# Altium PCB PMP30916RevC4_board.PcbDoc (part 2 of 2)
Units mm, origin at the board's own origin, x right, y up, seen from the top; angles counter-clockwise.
Board outline 58.42 x 31.75 mm, 4 copper layers (Top Layer, Layer 2, Layer 3, Bottom Layer), stack 1.787 mm thick; 61 components, 27 nets, 160 pads, 105 vias.
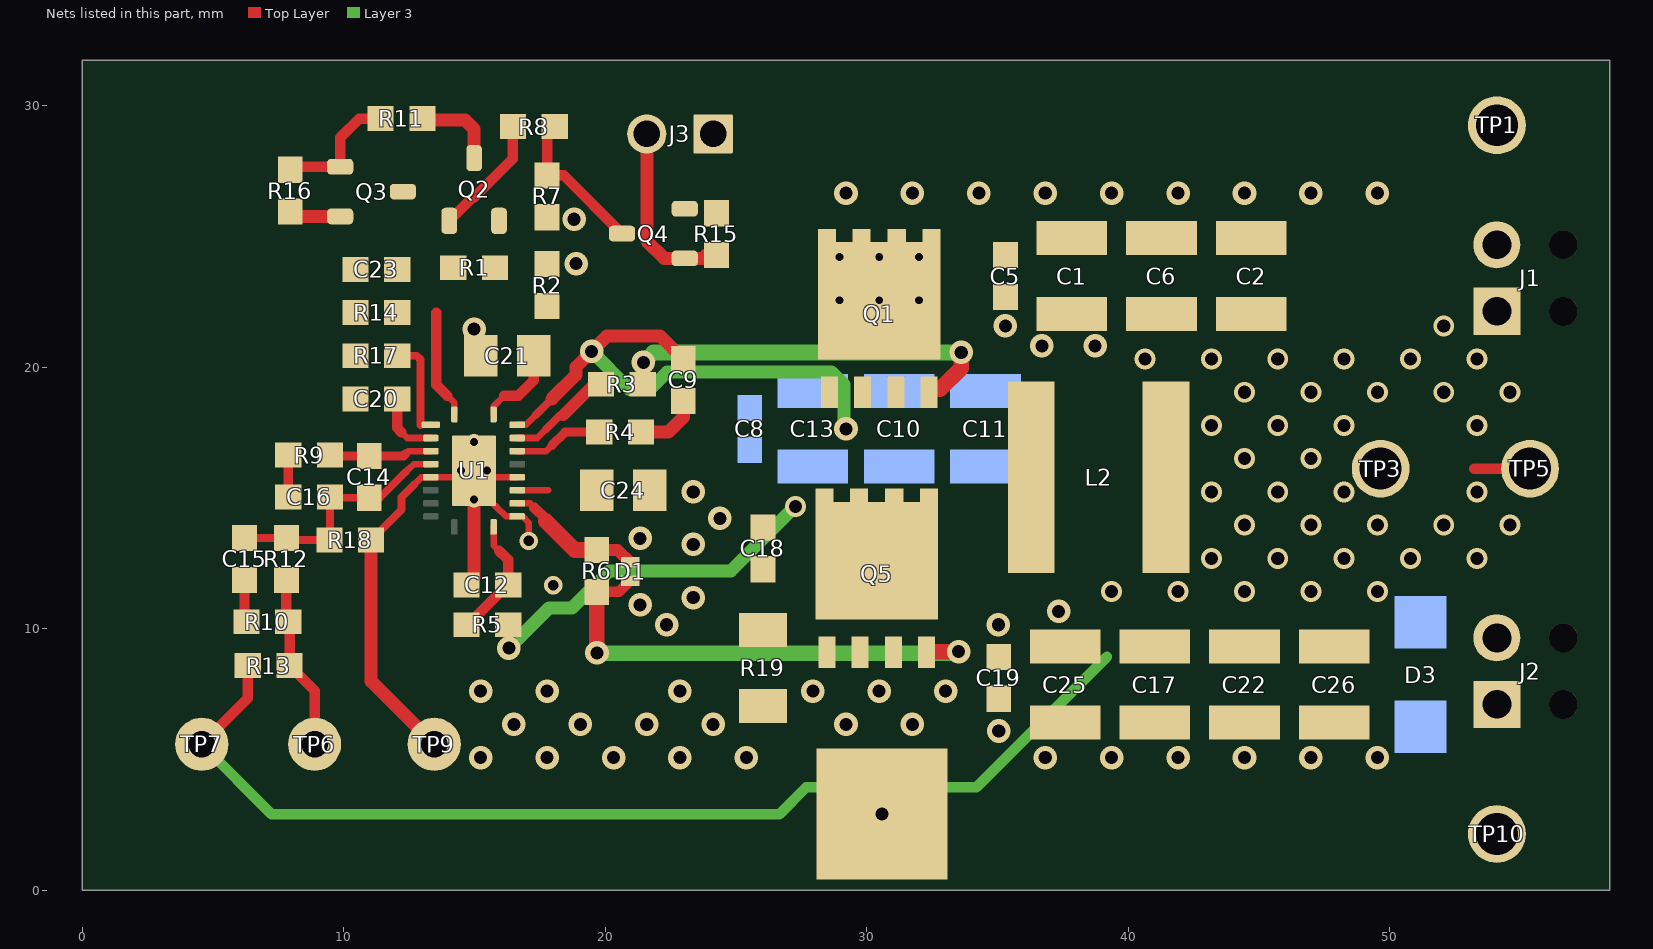
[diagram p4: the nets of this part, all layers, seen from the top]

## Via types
v1: diameter 0.9, hole 0.5, Top Layer to Bottom Layer, 35 vias
v2: diameter 0.8, hole 0.5, Top Layer to Bottom Layer, 31 vias
v3: diameter 0.9, hole 0.5, Top Layer to Bottom Layer, tented top, 18 vias
v4: diameter 0.8, hole 0.5, Top Layer to Bottom Layer, tented top, 7 vias
v5: diameter 0.7, hole 0.3, Top Layer to Bottom Layer, 6 vias
v6: diameter 0.6, hole 0.3, Top Layer to Bottom Layer, 4 vias
v7: diameter 0.7, hole 0.4, Top Layer to Bottom Layer, tented top, 2 vias
v8: diameter 0.9/0.9/0.9/0.8 (per signal layer), hole 0.5, Top Layer to Bottom Layer, tented bottom, 1 vias
v9: diameter 0.9, hole 0.5, Top Layer to Bottom Layer, tented both sides, 1 vias

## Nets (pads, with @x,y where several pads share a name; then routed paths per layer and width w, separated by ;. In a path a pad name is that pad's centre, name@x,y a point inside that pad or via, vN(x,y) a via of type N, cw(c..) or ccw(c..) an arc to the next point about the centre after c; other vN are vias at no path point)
GND: C1.2 C2.2 C5.2 C6.2 C17.2 C19.1 C22.2 C25.2 C26.2 D3.1 J1.1 J2.2 J3.1 L2.2 Q4.2 R13.2 R15.1 TP3.1 TP5.1 TP7.1 | length 44.1
  Top Layer w0.4: TP7.1@4.572,5.588 6.333,7.349 R13.2@6.333,8.598 ; 53.244,16.129 TP5.1@55.372,16.129 ; TP5.1@54.507,16.122 TP5.1@54.514,16.129
  Layer 3 w0.4: TP7.1@4.572,5.588 7.239,2.921 26.667,2.921 27.683,3.937 34.201,3.937 39.192,8.928
  other v2: 44.45,11.43 46.99,11.43 49.53,11.43 45.72,12.7 48.26,12.7 50.8,12.7 53.34,12.7 44.45,13.97 46.99,13.97 49.53,13.97 52.07,13.97 54.61,13.97 45.72,15.24 48.26,15.24 53.34,15.24 44.45,16.51 46.99,16.51 45.72,17.78 48.26,17.78 53.34,17.78 44.45,19.05 46.99,19.05 49.53,19.05 52.07,19.05 54.61,19.05 45.72,20.32 48.26,20.32 50.8,20.32 53.34,20.32 52.07,21.59
  other v3: 35.04,10.16 37.338,10.668 36.703,20.828 38.735,20.828 35.306,21.59
  other v4: 39.37,11.43 41.91,11.43 43.18,12.7 43.18,15.24 43.18,17.78 40.64,20.32 43.18,20.32
NetC1_1: C1.1 C2.1 C5.1 C6.1 C8.1 C10.1 C11.1 C13.1 J1.2 Q1.5 Q1.6 Q1.7 Q1.8 Q1.9 Q2.2 R1.2 R2.2 R7.2 TP1.1
  other v1: 18.886,23.97 29.21,26.67 31.75,26.67 34.29,26.67 36.83,26.67 39.37,26.67 41.91,26.67 44.45,26.67 46.99,26.67 49.53,26.67
  other v5: 28.956,22.568 30.48,22.568 32.004,22.568 28.956,24.219 30.48,24.219 32.004,24.219
  other v9: 18.811,25.668
NetC8_2: C8.2 C10.2 C11.2 C12.2 C13.2 C17.1 C19.2 C20.2 C21.2 C22.1 C23.2 C24.2 C25.1 C26.1 D3.2 J2.1 pad.12 Q3.2 Q5.1 Q5.2 Q5.3 R14.1 R16.1 R17.1 R18.1 R19.1 TP9.1 TP10.1 U1.6 U1.12 U1.15 U1.21@14.984,16.052 | length 23.9
  Top Layer w0.25: 12.7,15.526 12.977,15.802 U1.6@13.334,15.802 U1.21@14.334,15.802 ; U1.21@15.234,15.802 U1.15@16.634,15.802 ; U1.21@15.494,14.986 16.218,14.302 U1.12@16.634,14.302 16.844,14.302 17.082,14.064 v7(17.082,13.366) ; 15.834,14.686 15.834,14.691
  Top Layer w0.3: R18.1@11.051,13.401 12.209,14.559 12.209,15.035 12.7,15.526
  Top Layer w0.5: R16.1@7.958,25.958 8.141,25.775 Q3.2@9.866,25.775 ; R18.1@11.051,13.401 11.051,7.999 TP9.1@13.462,5.588 ; C12.2@14.694,11.684 14.984,11.974 v6(14.984,14.952) U1.21@14.984,16.052 U1.21@14.986,16.05
  other v1: 15.24,5.08 17.78,5.08 20.32,5.08 22.86,5.08 25.4,5.08 16.51,6.35 19.05,6.35 21.59,6.35 24.13,6.35 29.21,6.35 31.75,6.35 15.24,7.62 17.78,7.62 22.86,7.62 27.94,7.62 30.48,7.62 33.02,7.62 22.352,10.16 23.368,11.2 23.368,13.232 23.368,15.24
  other v3: 36.83,5.08 39.37,5.08 41.91,5.08 44.45,5.08 46.99,5.08 49.53,5.08 35.052,6.096 21.336,10.922 21.336,13.462 24.384,14.224 14.986,21.463
  other v6: 14.492,16.057 15.482,16.057 14.984,17.152
  other v7: 18.013,11.675
NetC9_1: C9.1 R4.2 | length 2.5
  Top Layer w0.5: R4.2@21.374,17.526 22.418,17.526 22.987,18.095 C9.1@22.987,18.72
NetC9_2: C9.2 C18.1 L2.1 Q1.1 Q1.2 Q1.3 Q5.5 Q5.6 Q5.7 Q5.8 Q5.9 R5.2 U1.19 | length 34.9
  Top Layer w0.25: U1.19@16.634,17.802 16.967,17.802 17.339,18.175
  Top Layer w0.3: 17.339,18.175 17.96,18.796 17.997,18.796
  Top Layer w0.5: R5.2@16.294,10.16 16.317,10.16 v3(16.317,9.264) ; 17.96,18.796 18.886,19.722 18.886,20.019 v1(19.482,20.614) 20.077,21.209 22.098,21.209 C9.2@22.987,20.32
  Layer 3 w0.5: v3(16.317,9.264) 17.857,10.804 18.739,10.804 20.15,12.216 24.802,12.216 v2(27.273,14.686) ; v1(19.482,20.614) 20.931,19.164 21.707,19.164 22.367,19.824 28.66,19.824 29.131,19.353 29.131,17.732 v8(29.21,17.653)
NetC12_1: C12.1 R5.1 U1.11 | length 4.7
  Top Layer w0.25: U1.11@15.734,13.902 15.734,13.2 15.939,12.995
  Top Layer w0.4: R5.1@14.694,10.16 14.753,10.16 16.277,11.684 C12.1@16.294,11.684 16.294,12.64 15.939,12.995
NetC14_1: C14.1 R9.2 U1.4 | length 3.9
  Top Layer w0.25: 12.357,16.69 12.469,16.802 U1.4@13.334,16.802
  Top Layer w0.35: R9.2@9.483,16.648 9.515,16.615 C14.1@10.976,16.615 12.282,16.615 12.357,16.69
NetC14_2: C14.2 C15.2 C16.2 R12.1 R18.2 U1.5 | length 9.3
  Top Layer w0.25: 12.357,15.99 12.483,16.115 12.49,16.115 12.677,16.302 U1.5@13.334,16.302
  Top Layer w0.3: C15.2@6.208,13.476 R12.1@7.808,13.476 7.883,13.401 R18.2@9.451,13.401 9.483,13.433 C16.2@9.483,15.051 9.518,15.015 C14.2@10.976,15.015 11.383,15.015 12.357,15.99
NetC15_1: C15.1 R10.1 | length 1.6
  Top Layer w0.4: C15.1@6.208,11.876 6.208,10.348 R10.1@6.283,10.273
NetC16_1: C16.1 R9.1 | length 1.6
  Top Layer w0.35: C16.1@7.883,15.051 R9.1@7.883,16.648
NetC18_2: C18.2 R19.2
NetC20_1: C20.1 U1.3 | length 2.6
  Top Layer w0.25: 12.209,17.526 12.433,17.302 U1.3@13.334,17.302
  Top Layer w0.4: C20.1@12.046,18.796 12.046,17.689 12.209,17.526
NetC21_1: C21.1 R2.1 U1.20 | length 3.2
  Top Layer w0.25: U1.20@15.734,18.202 15.734,18.507 16.143,18.916
  Top Layer w0.4: 16.143,18.916 16.68,18.916 17.272,19.508 C21.1@17.272,20.447
NetC23_1: C23.1 Q3.3 R1.1 R14.2 U1.1 | length 4.2
  Top Layer w0.25: 13.965,18.916 14.234,18.647 U1.1@14.234,18.202
  Top Layer w0.4: 13.539,22.098 13.539,19.342 13.965,18.916
NetC24_1: C24.1 U1.14 | length 1.2
  Top Layer w0.25: U1.14@16.634,15.302 17.814,15.302 17.818,15.306
NetD1_1: D1.1 R6.1 U1.13 | length 5.3
  Top Layer w0.25: U1.13@16.634,14.802 17.133,14.802 17.293,14.642
  Top Layer w0.4: 17.293,14.642 17.727,14.209 17.727,14.128
  Top Layer w0.45: R6.1@19.675,13.016 20.481,13.016 D1.1@20.955,12.542
  Top Layer w0.6: 17.727,14.128 18.839,13.016 R6.1@19.675,13.016
NetD1_2: D1.2 Q5.4 R6.2 | length 18.9
  Top Layer w0.4: R6.2@19.675,11.416 20.529,11.416 D1.2@20.955,11.842
  Top Layer w0.6: R6.2@19.675,11.416 19.675,9.097 v1@19.699,9.073 ; Q5.4@32.29,9.113 32.29,9.13 v1(33.513,9.13)
  Layer 3 w0.6: v1@19.699,9.073 33.456,9.073 v1(33.513,9.13)
  other v1: 19.687,9.085
NetJ3_2: J3.2 Q4.1 R15.2 | length 7.1
  Top Layer w0.5: J3.2@21.59,28.93 21.594,28.93 21.594,24.833 22.257,24.17 Q4.1@23.044,24.17 23.731,24.17 23.857,24.296 R15.2@24.257,24.296
NetQ1_4: Q1.4 R3.2 | length 15.4
  Top Layer w0.6: R3.2@21.436,19.357 21.436,20.166 v3(21.463,20.193) ; Q1.4@32.385,19.05 32.499,19.164 32.81,19.164 33.617,19.972 v1(33.617,20.574)
  Layer 3 w0.6: v3(21.463,20.193) 21.844,20.574 v1(33.617,20.574)
NetQ2_1: Q2.1 R8.2 | length 4.6
  Top Layer w0.4: Q2.1@14.039,25.607 14.938,26.506 14.989,26.506 16.472,27.989 R8.2@16.472,29.21
NetQ2_3: Q2.3 R11.2 | length 3.3
  Top Layer w0.5: R11.2@13.009,29.519 13.062,29.466 14.637,29.466 14.989,29.114 Q2.3@14.989,28.007
NetQ3_1: Q3.1 R11.1 R16.2 | length 4.9
  Top Layer w0.4: R16.2@7.958,27.558 8.075,27.675 Q3.1@9.866,27.675 9.866,28.794 10.591,29.519 R11.1@11.409,29.519
NetQ4_3: Q4.3 R7.1 R8.1 | length 5.8
  Top Layer w0.4: R8.1@18.072,29.21 17.78,28.918 R7.1@17.78,27.343 18.421,27.343 Q4.3@20.644,25.12
NetR3_1: R3.1 U1.18 | length 4.1
  Top Layer w0.25: U1.18@16.634,17.302 17.402,17.302 17.727,17.627
  Top Layer w0.3: 17.727,17.627 18.274,18.175 18.393,18.175
  Top Layer w0.45: 18.393,18.175 19.575,19.357 R3.1@19.836,19.357
NetR4_1: R4.1 U1.17 | length 3.4
  Top Layer w0.25: U1.17@16.634,16.802 17.745,16.802 17.96,17.018
  Top Layer w0.35: 17.96,17.018 18.468,17.526 R4.1@19.774,17.526
NetR10_2: R10.2 R12.2 R13.1 TP6.1 | length 6.7
  Top Layer w0.4: R12.2@7.808,11.876 7.808,10.348 R10.2@7.883,10.273 7.933,10.223 R13.1@7.933,8.598 8.89,7.641 TP6.1@8.89,5.588
NetR17_2: R17.2 U1.2 | length 3.8
  Top Layer w0.25: 12.938,17.803 U1.2@13.334,17.803
  Top Layer w0.3: R17.2@12.046,20.447 12.796,20.447 12.938,20.305 12.938,17.803
pads on no net: J1.MH1 J1.MH2 J2.MH1 J2.MH2 U1.7 U1.8 U1.9 U1.10 U1.16 U1.21@14.509,15.347 U1.21@14.509,16.757 U1.21@15.459,15.347 U1.21@15.459,16.757

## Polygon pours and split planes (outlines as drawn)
NetC1_1 on Bottom Layer "BOTTOM_LAYER_NETC1_1_P125" (solid, remove dead copper, pour order 125): 55.332,23.738 33.271,23.738 32.841,23.738 32.841,18.397 26.393,18.397 26.157,18.632 26.157,24.76 31.877,30.48 55.393,30.48
NetC8_2 on Bottom Layer "BOTTOM_LAYER_NETC8_2_P159" (solid, remove dead copper, pour order 159): 55.386,8.086 37.21,8.086 28.186,8.086 27.074,6.974 18.762,6.974 17.65,8.086 17.65,30.48 2.159,30.48 2.159,1.27 55.363,1.27
GND on Bottom Layer "BOTTOM_LAYER_GND_P157" (solid, remove dead copper, pour order 157): 55.372,23.241 37.883,23.241 37.883,10.468 37.338,9.923 37.338,8.432 55.372,8.432
NetC8_2 on Bottom Layer "BOTTOM_LAYER_NETC8_2_P121" (solid, remove dead copper, pour order 121): 36.625,6.57 18.391,6.57 14.157,10.804 14.157,21.678 15.489,23.01 24.384,23.01 24.384,17.365 36.625,17.365
NetC1_1 on Bottom Layer "BOTTOM_LAYER_NETC1_1_P135" (solid, remove dead copper, pour order 135): 27.599,26.67 24.98,24.051 24.91,17.952 36.625,17.952 36.625,26.67
NetC1_1 on Bottom Layer "BOTTOM_LAYER_NETC1_1_P133" (solid, remove dead copper, pour order 133): 32.457,30.48 15.234,30.48 15.234,23.37 30.507,23.37 32.457,25.32
NetC8_2 on Top Layer "TOP_LAYER_NETC8_2_P141" (solid, remove dead copper, pour order 141): 26.309,16.142 26.808,16.64 26.808,22.989 20.161,22.989 14.609,22.989 14.609,15.13 14.885,15.13 15.789,14.226 15.789,1.27 55.372,1.27 55.372,8.086 34.063,8.086 34.063,9.779 27.288,9.779 27.288,13.096 26.808,13.096 26.309,13.594
NetC9_2 on Top Layer "TOP_LAYER_NETC9_2_P016" (solid, remove dead copper, pour order 16): 32.766,10.287 ccw(c32.766,10.414) 32.893,10.414 32.893,11.771 cw(c33.035,11.771) 33.035,11.913 36.936,11.913 ccw(c36.936,12.191) 37.214,12.191 ccw(c34.303,12.236) 37.211,12.371 37.21,18.087 37.21,19.366 ccw(c36.892,19.366) 36.892,19.685 35.763,19.644 28.407,19.644 ccw(c28.407,19.304) 28.067,19.304 28.067,17.179 cw(c26.336,17.189) 27.553,15.958 cw(c25.656,17.625) 27.441,15.839 26.575,14.973 cw(c25.75,15.797) 25.75,14.631 ccw(c25.75,14.191) 25.31,14.191 25.31,13.631 ccw(c25.619,13.631) 25.619,13.322 26.245,13.322 cw(c26.245,11.991) 27.575,11.991 27.575,10.652 ccw(c27.94,10.652) 27.94,10.287
GND on Top Layer "TOP_LAYER_GND_P161" (solid, remove dead copper, pour order 161): 22.469,25.32 25.253,25.32 25.253,30.48 22.469,30.48
NetC1_1 on Top Layer "TOP_LAYER_NETC1_1_P149" (solid, remove dead copper, pour order 149): 15.282,23.335 19.334,23.335 19.334,26.244 19.289,26.289 15.32,26.289
NetC21_1 on Top Layer "TOP_LAYER_NETC21_1_P147" (solid, remove dead copper, pour order 147): 16.637,19.685 17.933,19.685 18.365,20.118 18.365,22.835 18.255,22.945 18.17,22.86 16.637,22.86
NetC8_2 on Top Layer "TOP_LAYER_NETC8_2_P145" (solid, remove dead copper, pour order 145): 13.557,1.27 2.159,1.27 2.159,30.48 13.236,30.48
GND on Top Layer "TOP_LAYER_GND_P129" (solid, remove dead copper, pour order 129): 37.883,11.399 34.29,11.399 34.29,8.432 55.372,8.432 55.372,23.241 38.608,23.241 34.717,23.241 34.717,20.249 37.883,20.249
NetC1_1 on Top Layer "TOP_LAYER_NETC1_1_P127" (solid, remove dead copper, pour order 127): 27.48,23.516 25.932,23.516 25.932,30.48 27.78,30.48 55.395,30.48 55.334,23.738 33.913,23.738 33.913,20.003 27.48,20.003
NetC23_1 on Top Layer "TOP_LAYER_NETC23_1_P053" (solid, remove dead copper, pour order 53): 14.666,24.357 13.813,24.357 13.216,24.954 13.216,27.556 11.477,27.556 11.477,21.661 14.398,21.661 14.398,23.196 14.609,23.407
NetC18_2 on Top Layer "TOP_LAYER_NETC18_2_P117" (solid, remove dead copper, pour order 117): 26.924,9.274 26.924,12.316 26.499,12.741 25.569,12.741 25.059,12.231 25.059,9.274
NetC24_1 on Top Layer "TOP_LAYER_NETC24_1_P107" (solid, remove dead copper, pour order 107): 20.368,14.478 18.299,14.478 17.727,15.051 17.339,15.051 17.339,15.561 17.961,16.184 20.368,16.184
NetC8_2 on Layer 3 "LAYER_3_NETC8_2_P155" (solid, remove dead copper, pour order 155): 32.527,1.27 55.372,1.27 55.372,8.086 33.979,8.086 33.992,11.842 37.338,11.842 37.338,20.025 34.167,20.025 34.167,23.274 33.416,23.301 22.908,23.301 22.908,30.479 2.159,30.48 2.159,1.27
GND on Layer 3 "LAYER_3_GND_P139" (solid, remove dead copper, pour order 139): 37.883,20.249 34.717,20.249 34.717,23.769 23.368,23.769 23.368,30.48 55.381,30.48 55.37,8.432 34.29,8.432 34.29,11.399 37.883,11.399
NetC8_2 on Layer 2 "LAYER_2_NETC8_2_P153" (solid, remove dead copper, pour order 153): 55.311,1.27 2.159,1.27 2.159,30.48 55.406,30.48

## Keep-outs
Keep-Out Layer:
  text ".Layer_Name" at 14.656,-21.806 h1.52

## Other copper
Top Layer:
  pour cut-out: 14.157,14.098 13.71,14.545 13.71,17.568 14.012,17.568 14.12,17.46
  pour cut-out: 16.305,14.65 15.824,15.13 15.824,17.759 16.268,18.203
  pour cut-out: 8.616,29.904
  text ".Layer_Name" at 14.656,-21.806 h1.52
Layer 3:
  region: 4.572,5.588
Bottom Layer:
  text ".Layer_Name" at 14.656,-21.806 h1.52

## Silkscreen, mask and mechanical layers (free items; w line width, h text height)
Top Overlay:
  text "'.PRJ_Number'.PCB_Rev" at 30.988,28.702 h2
  text "+VIN" at 57.277,27.051 h1 r90
  text "2020/08" at 1.524,24.357 h0.8 r90
  text "GND" at 57.277,17.653 h1 r90
  text "GND" at 57.277,12.065 h1 r90
  text "-VOUT" at 11.066,2.735 h1
  text "GND" at 3.175,2.572 h1
  text "NWA" at 7.588,2.572 h1
  text "LM5146 Inverting Buck Boost" at 1.143,0.762 h1
  text "-VOUT" at 57.277,0.508 h1 r90
  text ".Layer_Name" at 14.656,-21.806 h1.52
Bottom Overlay:
  text ".Layer_Name" at 14.656,-21.806 h1.52
Top Paste:
  text ".Layer_Name" at 14.656,-21.806 h1.52
Bottom Paste:
  text ".Layer_Name" at 14.656,-21.806 h1.52
Top Solder:
  text ".Layer_Name" at 14.656,-21.806 h1.52
  text ".Layer_Name" at 14.656,-21.806 h1.52
Bottom Solder:
  text "'.PRJ_Number'.PCB_Rev" at 50.701,28.016 h2
  text ".Layer_Name" at 14.656,-21.806 h1.52
Drill Guide:
  text ".Layer_Name" at 14.656,-21.806 h1.52
M1 Board Outline:
  the board outline again, w0.254
  text ".Layer_Name" at 14.656,-21.806 h1.52
M2 Board Dimensions:
  rectangle: 0,-6.985 3.175,-3.81
  rectangle: 3.175,-10.16 12.7,-6.985
  lines w0.178: 0,-6.985 25.4,-6.985 ; 3.175,-10.16 3.175,-3.81 ; 6.35,-10.16 6.35,-3.81 ; 12.7,-10.16 12.7,-3.81 ; 19.05,-10.16 19.05,-3.81 ; 0,-10.16 25.4,-10.16 25.4,-3.81 0,-3.81 0,-10.16
  text "'.Print_Date' '.Print_Time'" at 1.27,33.02 h1.5
  text ".Layer_Name" at 14.656,-21.806 h1.52
M3 3D STEP Top:
  text ".Layer_Name" at 14.656,-21.806 h1.52
M4 3D STEP Bottom:
  text ".Layer_Name" at 14.656,-21.806 h1.52
M5 Assembly Top:
  lines w0.254: -7.417,-23.626 160.223,-23.626 ; -7.417,-18.462 160.274,-18.462 ; -7.417,-13.297 -7.417,-28.791 94.31,-28.791 160.274,-28.791 160.274,-13.297 -7.404,-13.297 -7.404,-28.791 32.614,-28.791 ; 55.194,-28.791 55.194,-13.297 ; 87.376,-18.462 87.376,-13.297 ; 108.712,-18.462 108.712,-13.297 ; 124.511,-28.956 124.511,-23.804
  text "COMPONENTS MARKED 'DNP' SHOULD NOT BE POPULATED." at 29.299,-8.09 h1.52
  text "ASSEMBLY VARIANT:" at 29.286,-11.024 h1.52
  text ".VariantName" at 55.601,-11.024 h1.52
  text "PCB VIEWED FROM TOP SIDE" at -5.804,-16.654 h1.52
  text "BOARD #:" at 57.099,-16.654 h1.52
  text ".PRJ_Number" at 70.955,-16.654 h1.52
  text "REV:" at 92.405,-16.654 h1.52
  text ".PCB_Rev" at 99.809,-16.654 h1.52
  text "SVN REV:" at 113.69,-16.654 h1.52
  text ".VersionControl_RevNumber" at 126.543,-16.654 h1.52
  text "TID #:" at 57.099,-21.819 h1.52
  text ".TID" at 70.955,-21.819 h1.52
  text "PLOT NAME =" at -5.804,-27.034 h1.52
  text ".plot_File_Name" at 14.656,-27.034 h1.52
  text "GENERATED    :" at 57.15,-27.034 h1.52
  text ".Print_Date" at 79.235,-27.034 h1.52
  text ".Print_Time" at 97.752,-27.034 h1.52
  text "TEXAS INSTRUMENTS" at 129.87,-27.034 h1.52
M6 Assembly Bottom:
  lines w0.254: -7.429,-18.474 160.261,-18.474 ; -7.379,-23.639 160.261,-23.639 ; 28.334,-28.969 28.334,-23.817 ; 44.133,-18.474 44.133,-13.31 ; 65.468,-18.474 65.468,-13.31 ; 97.65,-28.804 97.65,-13.31 ; 120.231,-28.804 160.249,-28.804 160.249,-13.31 -7.429,-13.31 -7.429,-28.804 58.534,-28.804 160.261,-28.804 160.261,-13.31
  text "COMPONENTS MARKED 'DNP' SHOULD NOT BE POPULATED." at 154.991,-8.077 h1.52
  text ".VariantName" at 128.473,-11.024 h1.52
  text "ASSEMBLY VARIANT:" at 154.864,-11.024 h1.52
  text ".VersionControl_RevNumber" at 26.302,-16.667 h1.52
  text "SVN REV:" at 39.154,-16.667 h1.52
  text ".PCB_Rev" at 53.035,-16.667 h1.52
  text "REV:" at 60.439,-16.667 h1.52
  text ".PRJ_Number" at 81.89,-16.667 h1.52
  text "BOARD #:" at 95.745,-16.667 h1.52
  text "PCB VIEWED FROM BOTTOM SIDE" at 158.648,-16.667 h1.52
  text ".TID" at 81.89,-21.831 h1.52
  text "TID #:" at 95.745,-21.831 h1.52
  text "TEXAS INSTRUMENTS" at 22.974,-27.047 h1.52
  text ".Print_Time" at 55.093,-27.047 h1.52
  text ".Print_Date" at 73.609,-27.047 h1.52
  text "GENERATED    :" at 95.694,-27.047 h1.52
  text ".plot_File_Name" at 138.189,-27.047 h1.52
  text "PLOT NAME =" at 158.648,-27.047 h1.52
M9 Title Sheet:
  drawing of 57 lines, arcs and shapes, not listed
  text "1" at 18.792,204.127 h1.78
  text "2" at 82.182,204.127 h1.78
  text "3" at 145.411,204.127 h1.78
  text "4" at 209.08,204.127 h1.78
  text "5" at 272.555,204.127 h1.78
  text "6" at 336.182,204.127 h1.78
  text "A" at -10.579,175.095 h1.78
  text "A" at 365.341,175.095 h1.78
  text "B" at -10.579,114.643 h1.78
  text "B" at 365.341,114.643 h1.78
  text "C" at -10.579,54.318 h1.78
  text "C" at 365.341,54.318 h1.78
  text "PROJECT TITLE:" at 288.125,7.048 h1.14
  text ".PRJ_Title" at 289.395,3.662 h1.78
  text "DESIGNED FOR:" at 288.125,-0.597 h1.14
  text ".PRJ_Customer" at 289.395,-4.153 h1.78
  text "D" at -10.579,-5.88 h1.78
  text "D" at 365.341,-5.88 h1.78
  text "FILE NAME:" at 288.125,-8.217 h1.14
  text ".PCB_File_Name_No_Path" at 289.395,-11.265 h1.78
  text "Texas Instruments (TI) and/or its licensors do not warrant the accuracy or completeness of this specification" at 161.9,-15.376 h1.14
  text "ENGINEER:" at 288.125,-15.583 h1.14
  text "LAYOUT BY:" at 326.352,-15.583 h1.14
  text "or any information contained therein. TI and/or its licensors do not warrant that this design will meet" at 160.757,-18.237 h1.14
  text ".PRJ_Engineer" at 289.395,-19.52 h1.78
  text ".PCB_Layout" at 327.635,-19.52 h1.78
  text "the specifications, will be suitable for your application or fit for any particular purpose, or will operate in" at 160.757,-21.099 h1.14
  text ".Layer_Name" at 14.656,-21.806 h1.52
  text "ALTIUM DESIGNER VERSION:" at 326.352,-23.457 h1.14
  text "an implementation. TI and/or its licensors do not warrant that the design is production worthy. You should" at 160.757,-23.961 h1.14
  text "completely validate and test your design implementation to confirm the system functionality for your application." at 161.9,-26.822 h1.14
  text ".print_Scale" at 289.395,-26.843 h1.78
  text ".Application_BuildNumber" at 327.635,-26.843 h1.78
  text "1" at 18.792,-32.093 h1.78
  text "2" at 82.182,-32.093 h1.78
  text "3" at 145.411,-32.093 h1.78
  text "4" at 209.08,-32.093 h1.78
  text "5" at 272.555,-32.093 h1.78
  text "6" at 336.182,-32.093 h1.78
M10 Fab Notes:
  drawing of 189 lines, arcs and shapes, not listed
  text "DESIGN INFORMATION" at 314.503,161.447 h1.52
  text "MIN. TRACK WIDTH:" at 298.131,158.091 h1.52
  text "8" at 325.976,158.091 h1.52
  text "MIL" at 329.907,158.091 h1.52
  text "MIN. CLEARANCE:" at 298.131,154.938 h1.52
  text "0.2" at 324.452,154.938 h1.52
  text "mm" at 329.907,154.938 h1.52
  text "MIN. VIA PAD SIZE:" at 298.131,151.785 h1.52
  text "24" at 325.214,151.785 h1.52
  text "MIL" at 329.907,151.785 h1.52
  text "0.05mm (2MIL)" at 315.784,148.486 h1.52
  text "MINIMUM ANNULAR RING" at 289.769,148.277 h1.52
  text "EXTERNAL" at 333.768,148.277 h1.52
  text "PER" at 294.849,145.48 h1.52
  text "IPC-D-275 CLASS 2 LEVEL C" at 300.437,145.48 h1.52
  text "MIL, HOLES" at 338.238,142.928 h1.52
  text "+/-" at 328.27,142.709 h1.52
  text "+/-" at 349.961,142.709 h1.52
  text "REGISTRATION TOLERANCES:" at 289.769,142.682 h1.52
  text "METAL" at 320.243,142.682 h1.52
  text "5" at 334.879,142.683 h1.52
  text "3" at 356.037,142.683 h1.52
  text "MIL" at 358.99,142.682 h1.52
  text "HOLE SIZE TOLERANCE (UNLESS OTHERWISE SPECIFIED):" at 289.769,140.185 h1.52
  text "+/-" at 349.961,140.112 h1.52
  text "3" at 356.037,140.085 h1.52
  text "MIL" at 358.99,140.085 h1.52
  text "MATERIAL:" at 287.87,136.589 h1.52
  text "FR-4 High Tg" at 312.926,133.324 h1.52
  text "X" at 309.257,133.122 h1.52
  text "FR-408" at 298.563,133.007 h1.52
  text "OTHER" at 336.358,133.007 h1.52
  text "62 MIL (1.6mm) +/-10%" at 306.694,129.374 h1.52
  text "X" at 303.643,129.312 h1.52
  text "THICKNESS:" at 289.769,129.165 h1.52
  text "OTHER" at 339.33,129.165 h1.52
  text "TOLERANCE:" at 289.769,125.652 h1.52
  text "X" at 311.314,125.652 h1.52
  text "ANSI IPC-6012 TYPE 3 CLASS 2" at 315.836,125.652 h1.52
  text "OTHER +/-" at 315.835,121.989 h1.52
  text "BOW & TWIST:" at 289.769,118.302 h1.52
  text "X" at 311.314,118.302 h1.52
  text "ANSI IPC-6012 TYPE 3 CLASS 2" at 315.836,118.302 h1.52
  text "OTHER +/-" at 315.835,114.576 h1.52
  text "DRILLING:" at 287.87,111.258 h1.52
  text "NC_DRILL FILES" at 332.599,108.586 h1.52
  text "REFERENCE:" at 289.769,108.486 h1.52
  text "X" at 306.463,108.484 h1.52
  text "AS SHOWN" at 310.984,108.486 h1.52
  text "X" at 329.348,108.486 h1.52
  text "OTHER" at 340.168,104.873 h1.52
  text "PTH COPPER THICKNESS:" at 289.761,104.783 h1.52
  text "X" at 318.697,104.783 h1.52
  text "20-30 um" at 321.948,104.783 h1.52
  text "BOARD FINISH:" at 287.87,101.034 h1.52
  text "SILKSCREEN:" at 291.812,98.237 h1.52
  text "X" at 316.14,98.237 h1.52
  text "TOP" at 319.112,98.237 h1.52
  text "X" at 329.094,98.237 h1.52
  text "BOTTOM" at 332.091,98.237 h1.52
  text "SILKSCREEN COLOR:" at 291.812,94.295 h1.52
  text "X" at 316.115,94.295 h1.52
  text "WHITE" at 319.112,94.295 h1.52
  text "OTHER" at 332.091,94.295 h1.52
  text "X" at 319.442,90.652 h1.52
  text "GREEN" at 322.439,90.652 h1.52
  text "OTHER" at 338.136,90.652 h1.52
  text "SOLDER RESIST COLOR:" at 291.812,90.477 h1.52
  text "X" at 319.442,86.734 h1.52
  text "MATTE" at 322.439,86.734 h1.52
  text "SEMI-GLOSS" at 338.125,86.717 h1.52
  text "IMMERSION GOLD (ENIG)" at 314.819,82.345 h1.52
  text "ENEPIG" at 348.793,82.162 h1.52
  text "SURFACE FINISH:" at 287.87,82.136 h1.52
  text "X" at 310.298,82.136 h1.52
  text "IMM. TIN/SILVER OR EQUIV" at 296.24,78.649 h1.52
  text "OTHER" at 332.599,78.549 h1.52
  text "ARRAY/PANEL:" at 287.87,74.602 h1.52
  text "CUT AND TRIM PER M1 BOARD OUTLINE" at 314.819,74.393 h1.52
  text "N.C. ROUTE" at 314.819,70.94 h1.52
  text "X" at 332.295,70.94 h1.52
  text "V. SCORE" at 336.816,70.94 h1.52
  text "CERTIFICATION:" at 287.87,67.66 h1.52
  text "MATERIALS AND WORKMANSHIP FOR ALL PCBS" at 306.285,67.66 h1.52
  text "TO MEET OR EXCEED THE REQUIREMENTS OF:" at 306.285,65.271 h1.52
  text "X" at 297.078,62.003 h1.52
  text "ANSI IPC-A-600F CLASS ->" at 300.329,62.003 h1.52
  text "X" at 342.188,62.003 h1.52
  text "2" at 344.982,62.003 h1.52
  text "1" at 336.981,61.965 h1.52
  text "3" at 353.973,61.965 h1.52
  text "X" at 317.702,58.252 h1.52
  text "RoHS" at 320.953,58.252 h1.52
  text "OTHER" at 337.321,58.252 h1.52
  text "PER ORDER" at 347.407,58.252 h1.52
  text "ALL BOARDS MUST MEET OR EXCEED UL94-V0 REQUIREMENTS." at 288.569,54.345 h1.52
  text "PCB MUST BEAR THE UL94V-0 UL REGISTERED MATERIAL ID NUMBER" at 288.569,51.397 h1.52
  text "ADDITIONAL REQUIREMENTS:" at 287.87,47.094 h1.52
  text "MICROSECTION:" at 289.769,44.373 h1.52
  text "YES" at 312.775,44.373 h1.52
  text "REQUIRED" at 334.657,40.707 h1.52
  text "BARE BOARD ELEC. TEST:" at 289.769,40.634 h1.52
  text "NONE" at 322.935,40.634 h1.52
  text "X" at 331.66,40.634 h1.52
  text "PER ORDER" at 349.693,40.634 h1.52
  text "XX MIL VIAS REQUIRE NON-CONDUCTIVE FILL AND PLANARIZE" at 294.04,35.428 h1.5
  text "XX MIL VIAS REQUIRE CONDUCTIVE FILL AND PLANARIZE" at 294.243,32.787 h1.52
  text "OUTER XX MIL TRACES REQUIRE 50 OHM SINGLE-ENDED IMPEDANCE" at 294.218,28.637 h1.47
  text "LAYER 2 & 3 (INNER LAYERS) XX MIL WIDE, XX MIL SPACE / TRACES REQUIRE 100 OHM DIFFERENTIAL IMPEDANCE" at 294.015,22.65 h1.52
  text ".Layer_Name" at 14.656,-21.806 h1.52
M11 Gerber Information:
  lines w0.254: -7.417,-23.626 160.223,-23.626 ; -7.417,-18.462 160.274,-18.462 ; -7.417,-13.297 -7.417,-28.791 94.31,-28.791 160.274,-28.791 160.274,-13.297 -7.404,-13.297 -7.404,-28.791 32.614,-28.791 ; 55.194,-28.791 55.194,-13.297 ; 87.376,-18.462 87.376,-13.297 ; 108.712,-18.462 108.712,-13.297 ; 124.511,-28.956 124.511,-23.804
  text "ALL ARTWORK VIEWED FROM TOP SIDE" at -5.804,-16.654 h1.52
  text "BOARD #:" at 57.099,-16.654 h1.52
  text ".PRJ_Number" at 70.955,-16.654 h1.52
  text "REV:" at 92.405,-16.654 h1.52
  text ".PCB_Rev" at 99.809,-16.654 h1.52
  text "SVN REV:" at 113.69,-16.654 h1.52
  text ".VersionControl_RevNumber" at 126.543,-16.654 h1.52
  text "LAYER NAME =" at -5.804,-21.806 h1.52
  text "TID #:" at 57.099,-21.819 h1.52
  text ".TID" at 70.955,-21.819 h1.52
  text "PLOT NAME =" at -5.804,-27.034 h1.52
  text ".plot_File_Name" at 14.656,-27.034 h1.52
  text "GENERATED    :" at 57.15,-27.034 h1.52
  text ".Print_Date" at 79.235,-27.034 h1.52
  text ".Print_Time" at 97.752,-27.034 h1.52
  text "TEXAS INSTRUMENTS" at 129.87,-27.034 h1.52
M12 Stackup:
  drawing of 295 lines, arcs and shapes, not listed
  text "Layer" at 249.119,181.737 h1.52
  text "Name" at 259.531,181.737 h1.52
  text "Material" at 283.147,181.737 h1.52
  text "Thickness" at 304.985,181.737 h1.52
  text "Constant" at 321.49,181.737 h1.52
  text "Board Layer Stack" at 335.965,181.737 h1.52
  text "Top Overlay" at 259.531,178.689 h1.52
  text "Top Solder" at 259.531,175.641 h1.52
  text "Solder Resist" at 283.147,175.641 h1.52
  text "0.40mil" at 304.985,175.641 h1.52
  text "3.5" at 321.49,175.641 h1.52
  text "1" at 249.119,172.593 h1.52
  text "Top Layer" at 259.531,172.593 h1.52
  text "Copper" at 283.147,172.593 h1.52
  text "1.40mil" at 304.985,172.593 h1.52
  text "Dielectric 1" at 259.531,169.545 h1.52
  text "PP-006" at 283.147,169.545 h1.52
  text "2.80mil" at 304.985,169.545 h1.52
  text "4.1" at 321.49,169.545 h1.52
  text "2" at 249.119,166.497 h1.52
  text "Layer 2" at 259.531,166.497 h1.52
  text "Copper" at 283.147,166.497 h1.52
  text "1.38mil" at 304.985,166.497 h1.52
  text "Dielectric1" at 259.531,163.449 h1.52
  text "FR-4" at 283.147,163.449 h1.52
  text "59.20mil" at 304.985,163.449 h1.52
  text "4.8" at 321.49,163.449 h1.52
  text "3" at 249.119,160.401 h1.52
  text "Layer 3" at 259.531,160.401 h1.52
  text "Copper" at 283.147,160.401 h1.52
  text "1.38mil" at 304.985,160.401 h1.52
  text "Dielectric 2" at 259.531,157.353 h1.52
  text "PP-006" at 283.147,157.353 h1.52
  text "2.80mil" at 304.985,157.353 h1.52
  text "4.1" at 321.49,157.353 h1.52
  text "4" at 249.119,154.305 h1.52
  text "Bottom Layer" at 259.531,154.305 h1.52
  text "Copper" at 283.147,154.305 h1.52
  text "1.40mil" at 304.985,154.305 h1.52
  text "Bottom Solder" at 259.531,151.257 h1.52
  text "Solder Resist" at 283.147,151.257 h1.52
  text "0.40mil" at 304.985,151.257 h1.52
  text "3.5" at 321.49,151.257 h1.52
  text "Bottom Overlay" at 259.531,148.209 h1.52
  text ".Layer_Name" at 14.656,-21.806 h1.52
M13 Component Bodies Top:
  text ".Layer_Name" at 14.656,-21.806 h1.52
M14 Component Bodies Bottom:
  text ".Layer_Name" at 14.656,-21.806 h1.52
M15 Courtyards Top:
  text ".Layer_Name" at 14.656,-21.806 h1.52
M16 Courtyards Bottom:
  text ".Layer_Name" at 14.656,-21.806 h1.52
Drill Drawing:
  circle w0.254: c136.241,81.204 r0.703
  lines w0.254: 135.538,68.204 135.89,68.204 135.89,67.852 136.593,67.852 136.593,68.204 136.944,68.204 136.944,68.906 136.593,68.906 136.593,69.258 135.89,69.258 135.89,68.906 135.538,68.906 135.538,68.204 ; 135.538,72.42 136.944,72.42 136.241,71.015 135.538,72.42 ; 135.538,74.177 136.944,74.177 136.944,75.582 135.538,75.582 135.538,74.177 ; 135.538,77.339 136.241,77.691 136.944,77.339 136.593,78.042 136.944,78.745 136.241,78.393 135.538,78.745 135.89,78.042 135.538,77.339 ; 135.538,83.664 135.538,84.015 135.89,84.367 135.538,84.718 135.538,85.069 135.89,85.069 136.241,84.718 136.593,85.069 136.944,85.069 136.944,84.718 136.593,84.367 136.944,84.015 136.944,83.664 136.593,83.664 136.241,84.015 135.89,83.664 135.538,83.664 ; 135.538,87.529 136.241,86.826 136.944,87.529 136.241,88.232 135.538,87.529
  lines w0.305: 134.264,66.904 216.362,66.904 ; 134.264,89.04 216.362,89.04 ; 142.85,63.741 142.85,92.202 ; 151.287,63.741 151.287,92.202 ; 167.453,63.741 167.453,92.202 ; 174.037,63.741 174.037,92.202 ; 183.568,63.741 183.568,92.202 ; 201.972,63.741 201.972,92.202 ; 134.264,63.741 216.362,63.741 216.362,92.202 134.264,92.202 134.264,63.741
  text "Symbol" at 136.162,89.988 h1.83
  text "Quantity" at 143.799,89.988 h1.83
  text "Finished Hole Size" at 152.235,89.988 h1.83
  text "Plated" at 168.402,89.988 h1.83
  text "Hole Type" at 174.986,89.988 h1.83
  text "Drill Layer Pair" at 184.517,89.988 h1.83
  text "Hole Tolerance" at 202.92,89.988 h1.83
  text "4" at 143.799,86.826 h1.52
  text "43.31mil (1.100mm)" at 152.235,86.826 h1.52
  text "NPTH" at 168.402,86.826 h1.52
  text "Round" at 174.986,86.826 h1.52
  text "Top Layer - Bottom Layer" at 184.517,86.826 h1.52
  text "10" at 143.799,83.664 h1.52
  text "11.81mil (0.300mm)" at 152.235,83.664 h1.52
  text "PTH" at 168.402,83.664 h1.52
  text "Round" at 174.986,83.664 h1.52
  text "Top Layer - Bottom Layer" at 184.517,83.664 h1.52
  text "2" at 143.799,80.501 h1.52
  text "15.75mil (0.400mm)" at 152.235,80.501 h1.52
  text "PTH" at 168.402,80.501 h1.52
  text "Round" at 174.986,80.501 h1.52
  text "Top Layer - Bottom Layer" at 184.517,80.501 h1.52
  text "94" at 143.799,77.339 h1.52
  text "19.69mil (0.500mm)" at 152.235,77.339 h1.52
  text "PTH" at 168.402,77.339 h1.52
  text "Round" at 174.986,77.339 h1.52
  text "Top Layer - Bottom Layer" at 184.517,77.339 h1.52
  text "5" at 143.799,74.177 h1.52
  text "40.00mil (1.016mm)" at 152.235,74.177 h1.52
  text "PTH" at 168.402,74.177 h1.52
  text "Round" at 174.986,74.177 h1.52
  text "Top Layer - Bottom Layer" at 184.517,74.177 h1.52
  text "4" at 143.799,71.015 h1.52
  text "43.31mil (1.100mm)" at 152.235,71.015 h1.52
  text "PTH" at 168.402,71.015 h1.52
  text "Round" at 174.986,71.015 h1.52
  text "Top Layer - Bottom Layer" at 184.517,71.015 h1.52
  text "4" at 143.799,67.852 h1.52
  text "63.00mil (1.600mm)" at 152.235,67.852 h1.52
  text "PTH" at 168.402,67.852 h1.52
  text "Round" at 174.986,67.852 h1.52
  text "Top Layer - Bottom Layer" at 184.517,67.852 h1.52
  text "123 Total" at 143.799,64.69 h1.52
  text ".Layer_Name" at 14.656,-21.806 h1.52
M17 Embedded Cavity:
  text ".Layer_Name" at 14.656,-21.806 h1.52
M18 Embedded Assembly:
  text ".Layer_Name" at 14.656,-21.806 h1.52
M19 Embedded Keepout:
  text ".Layer_Name" at 14.656,-21.806 h1.52

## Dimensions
0,-10.16 to 25.4,-10.16 on M2 Board Dimensions
0,0 to 0,31.75 on M2 Board Dimensions
0,0 to 58.42,0 on M2 Board Dimensions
